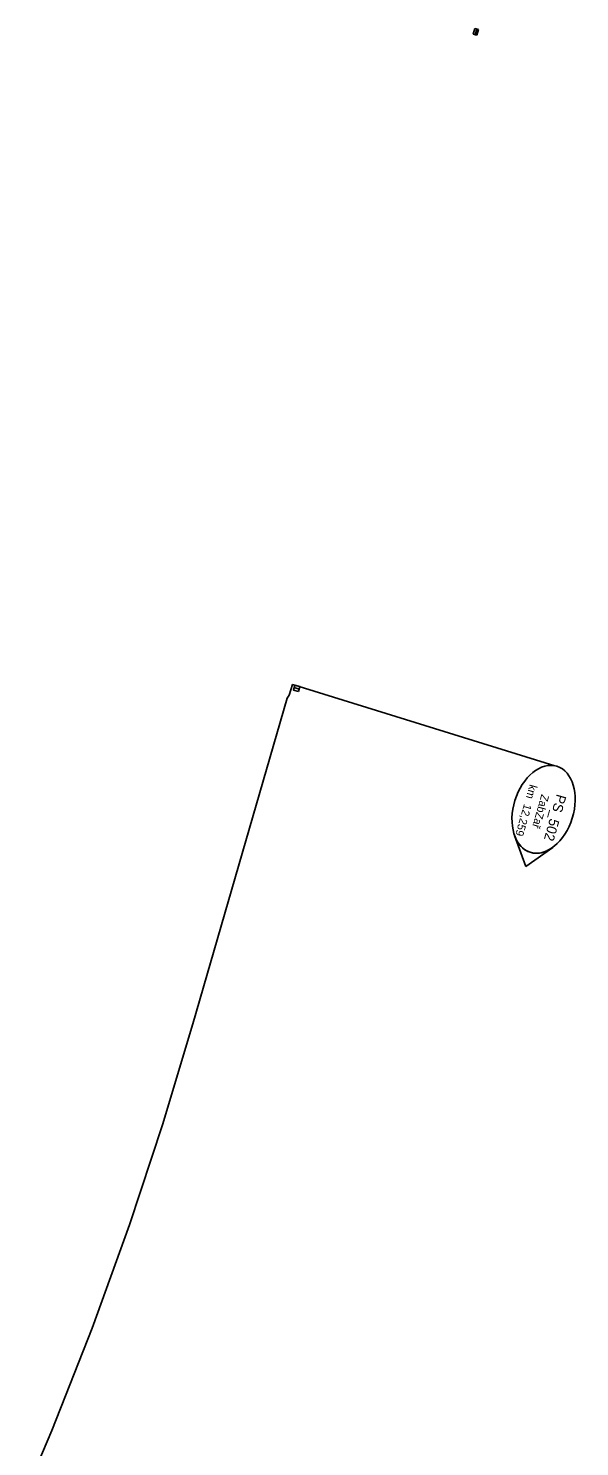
# Model space of a CAD drawing. Extents: x -743359 to -742769, y -1127804 to -1126284.
# Drawn here: x -742907.1 to -742769.4, y -1126638.5 to -1126284.1 of the extents above; entities that cross this region are included whole.
import ezdxf

# ---------------------------------------------------------------- set-up
doc = ezdxf.new("R2010")
doc.units = 0
for name, color, linetype in [('_Násyp', 7, 'Continuous'), ('_Zabezpečovací zařízení', 7, 'Continuous'), ('_Zabezpečovací zařízení_trasa', 7, 'Continuous'), ('bublina_fialová_čára_tenká', 7, 'Continuous'), ('bublina_růžová_230_čára_tučná', 7, 'Continuous')]:
    doc.layers.add(name, color=color, linetype=linetype)

msp = doc.modelspace()

# ---------------------------------------------------------------- linework, layer by layer
at = {"layer": '_Zabezpečovací zařízení'}
for p, q in [((-742796.03, -1126285.56), (-742795.61, -1126284.12)), ((-742796.03, -1126285.56), (-742795.61, -1126284.12)), ((-742795.07, -1126285.84), (-742796.03, -1126285.56)), ((-742795.07, -1126285.84), (-742796.03, -1126285.56)), ((-742795.61, -1126284.12), (-742794.65, -1126284.4)), ((-742795.61, -1126284.12), (-742794.65, -1126284.4)), ((-742795.55, -1126285.7), (-742795.13, -1126284.26)), ((-742795.55, -1126285.7), (-742795.13, -1126284.26)), ((-742794.65, -1126284.4), (-742795.07, -1126285.84)), ((-742794.65, -1126284.4), (-742795.07, -1126285.84)), ((-742840.55, -1126448.27), (-742840.9, -1126449.47)), ((-742840.9, -1126449.47), (-742839.7, -1126449.81)), ((-742840.73, -1126448.87), (-742839.53, -1126449.21)), ((-742839.35, -1126448.61), (-742840.55, -1126448.27)), ((-742839.7, -1126449.81), (-742839.35, -1126448.61))]:
    msp.add_line(p, q, dxfattribs=at)
msp.add_lwpolyline([(-742839.7, -1126449.81), (-742839.53, -1126449.21), (-742840.73, -1126448.87), (-742840.9, -1126449.47), (-742839.7, -1126449.81)], dxfattribs=at)
at = {"layer": '_Zabezpečovací zařízení_trasa'}
msp.add_lwpolyline([(-742840.55, -1126448.27), (-742841.15, -1126448.09), (-742841.97, -1126450.76), (-742842.49, -1126451.53), (-742852.79, -1126487.17), (-742866.03, -1126532.91), (-742873.66, -1126558.12), (-742881.91, -1126583.11), (-742891.24, -1126608.96), (-742901.32, -1126634.54), (-742907.14, -1126648.25)], dxfattribs=at)
at = {"layer": 'bublina_fialová_čára_tenká'}
msp.add_line((-742775.61, -1126468.39), (-742840.55, -1126448.27), dxfattribs=at)
at = {"layer": 'bublina_růžová_230_čára_tučná'}
for p, q in [((-742782.86, -1126493.6), (-742785.67, -1126485.84)), ((-742782.86, -1126493.6), (-742785.67, -1126485.84)), ((-742776.16, -1126488.78), (-742782.86, -1126493.6)), ((-742776.16, -1126488.78), (-742782.86, -1126493.6))]:
    msp.add_line(p, q, dxfattribs=at)
msp.add_ellipse((-742778.43, -1126479.27), major_axis=(3.32, 10.75), ratio=0.666667, dxfattribs=at)
msp.add_ellipse((-742778.43, -1126479.27), major_axis=(-3.32, -10.75), ratio=0.666473, start_param=5.557317, end_param=7.009053, dxfattribs=at)

# ---------------------------------------------------------------- texts
at = {"layer": '_Násyp'}
for s, height, p in [('km  12,259', 2, (-742781.88, -1126472.92)), ('ZabZař', 2, (-742778.94, -1126475.38)), ('PS_502', 2.5, (-742775.1, -1126475.33))]:
    msp.add_text(s, height=height, rotation=253.9997, dxfattribs=at).set_placement(p)

doc.saveas('drawing.dxf')
